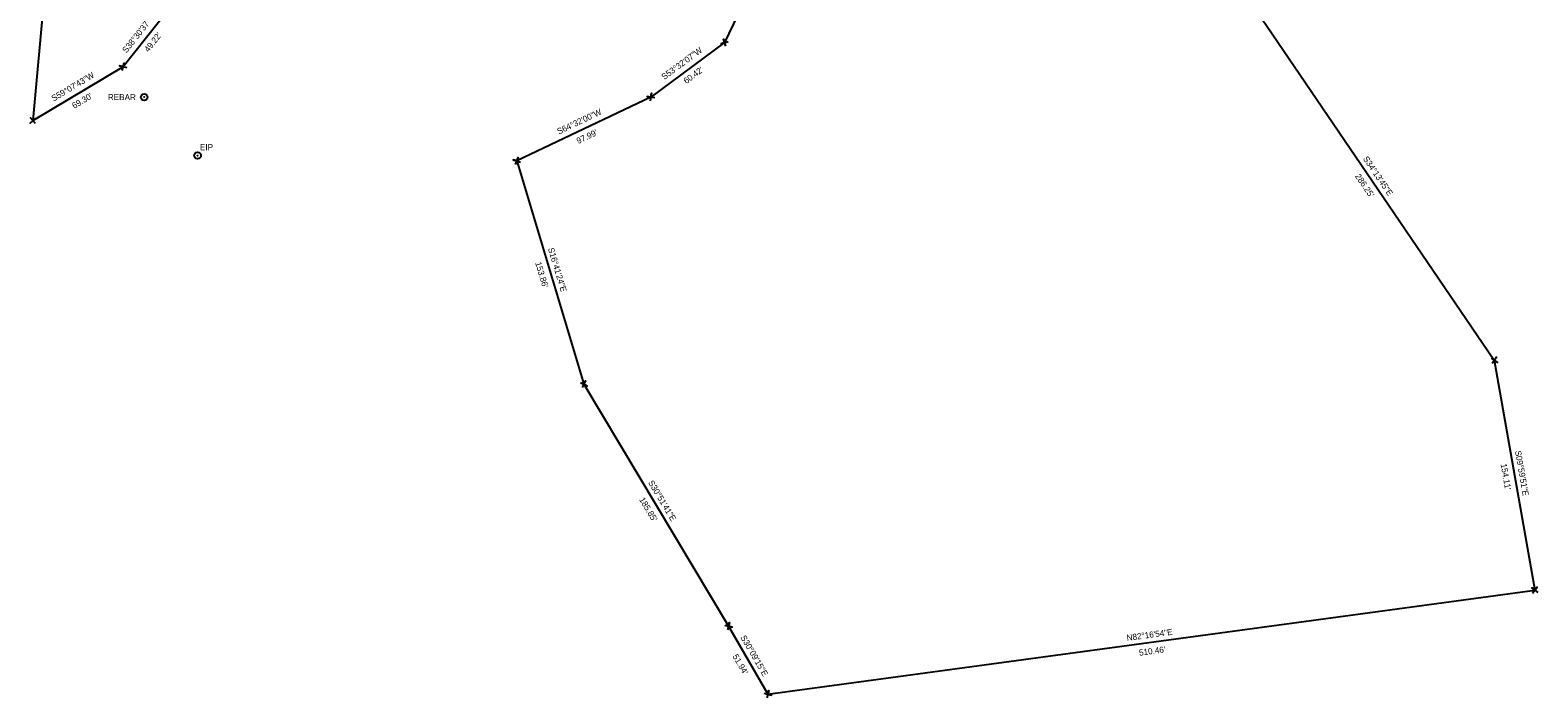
# Model space of a CAD drawing. Extents: x 860808 to 861835, y 630123 to 631311.
# Drawn here: x 860840 to 861835, y 630123 to 630563 of the extents above; entities that cross this region are included whole.
import ezdxf

# ---------------------------------------------------------------- set-up
doc = ezdxf.new("R2010")
doc.units = 0
for name, color, linetype in [('Exist Property Corner CELL', 7, 'Continuous'), ('Exist Property Iron Pin CELL', 7, 'Continuous'), ('Exist Property Line', 7, 'Continuous'), ('Exist Property Text', 7, 'Continuous')]:
    doc.layers.add(name, color=color, linetype=linetype)

msp = doc.modelspace()

# ---------------------------------------------------------------- linework, layer by layer
at = {"layer": 'Exist Property Corner CELL'}
for p, q in [((861298.48, 630555), (861298.48, 630555)), ((860901.8, 630539.13), (860901.8, 630539.13)), ((861249.89, 630519.09), (861249.89, 630519.09)), ((860842.32, 630503.57), (860842.32, 630503.57)), ((861161.42, 630476.96), (861161.42, 630476.96)), ((861806.12, 630345.46), (861806.12, 630345.46)), ((861205.61, 630329.58), (861205.61, 630329.58)), ((861832.87, 630193.69), (861832.87, 630193.69)), ((861300.94, 630170.04), (861300.94, 630170.04)), ((861327.03, 630125.13), (861327.03, 630125.13))]:
    msp.add_line(p, q, dxfattribs=at)
for points in [[(861299.32, 630552.64), (861297.65, 630557.36), (861298.48, 630555), (861296.12, 630554.16), (861300.84, 630555.83)], [(860901.19, 630536.71), (860902.42, 630541.56), (860901.8, 630539.13), (860899.38, 630539.74), (860904.23, 630538.52)], [(861249.52, 630516.62), (861250.26, 630521.56), (861249.89, 630519.09), (861247.42, 630519.46), (861252.36, 630518.72)], [(860843.92, 630501.65), (860840.73, 630505.5), (860842.32, 630503.57), (860840.4, 630501.98), (860844.25, 630505.17)], [(861160.58, 630474.6), (861162.26, 630479.31), (861161.42, 630476.96), (861159.07, 630477.79), (861163.78, 630476.12)], [(861804.07, 630346.89), (861808.16, 630344.02), (861806.12, 630345.46), (861807.55, 630347.5), (861804.68, 630343.41)], [(861203.41, 630330.76), (861207.81, 630328.39), (861205.61, 630329.58), (861206.8, 630331.78), (861204.42, 630327.38)], [(861831.35, 630191.7), (861834.38, 630195.67), (861832.87, 630193.69), (861830.88, 630195.2), (861834.86, 630192.17)], [(861298.53, 630170.68), (861303.36, 630169.4), (861300.94, 630170.04), (861301.58, 630172.46), (861300.3, 630167.62)], [(861324.62, 630125.77), (861329.45, 630124.49), (861327.03, 630125.13), (861327.68, 630127.55), (861326.39, 630122.71)]]:
    msp.add_lwpolyline(points, dxfattribs=at)
at = {"layer": 'Exist Property Iron Pin CELL'}
for centre, radius in [((860915.56, 630519.09), 2.2), ((860915.56, 630519.09), 0.0707), ((860950.86, 630480.5), 2.2), ((860950.86, 630480.5), 0.0707)]:
    msp.add_circle(centre, radius, dxfattribs=at)
at = {"layer": 'Exist Property Line'}
for p, q in [((860842.32, 630503.57), (860869, 630793.55)), ((861319.81, 630599.73), (861298.48, 630555)), ((860932.45, 630577.65), (860901.8, 630539.13)), ((861645.1, 630582.13), (861806.12, 630345.46)), ((861298.48, 630555), (861249.89, 630519.09)), ((860901.8, 630539.13), (860842.32, 630503.57)), ((861249.89, 630519.09), (861161.42, 630476.96)), ((861161.42, 630476.96), (861205.61, 630329.58)), ((861806.12, 630345.46), (861832.87, 630193.69)), ((861205.61, 630329.58), (861300.94, 630170.04)), ((861327.03, 630125.13), (861832.87, 630193.69)), ((861300.94, 630170.04), (861327.03, 630125.13))]:
    msp.add_line(p, q, dxfattribs=at)

# ---------------------------------------------------------------- texts
at = {"layer": 'Exist Property Text'}
for s, rotation, p in [('S38°30\'37"W', 51.48979, (860903.89, 630547.82)), ("49.22'", 51.48979, (860918.41, 630548.4)), ('S53°32\'07"W', 36.4647, (861258.66, 630530.27)), ("60.42'", 36.4647, (861273.2, 630527.59)), ('S59°07\'43"W', 30.87146, (860855.95, 630516.12)), ("69.30'", 30.87146, (860869.51, 630511.23)), ('S64°32\'00"W', 25.46664, (861189.12, 630494.33)), ("97.99'", 25.46664, (861201.94, 630488.09)), ('S34°13\'45"E', 304.22914, (861719.3, 630478.39)), ("286.25'", 304.22914, (861714.1, 630466.84)), ('S16°41\'24"E', 286.68998, (861181.9, 630419.09)), ("153.86'", 286.68998, (861173.46, 630409.64)), ('S09°59\'51"E', 279.99748, (861819.74, 630285.47)), ("154.11'", 279.99748, (861810.29, 630276.86)), ('S30°51\'41"E', 300.86136, (861247.84, 630264.76)), ("185.85'", 300.86136, (861241.97, 630253.52)), ('N82°16\'54"E', 7.71831, (861563.92, 630160.26)), ('S30°09\'15"E', 300.15414, (861308.74, 630162.6)), ("51.94'", 300.15414, (861303.51, 630150.09)), ("510.46'", 7.71831, (861572.09, 630150.47))]:
    msp.add_text(s, height=4.02, rotation=rotation, dxfattribs=at).set_placement(p)
for s, p in [('REBAR', (860891.64, 630517.05)), ('EIP', (860952.36, 630484.02))]:
    msp.add_text(s, height=4.02, dxfattribs=at).set_placement(p)

doc.saveas('drawing.dxf')
